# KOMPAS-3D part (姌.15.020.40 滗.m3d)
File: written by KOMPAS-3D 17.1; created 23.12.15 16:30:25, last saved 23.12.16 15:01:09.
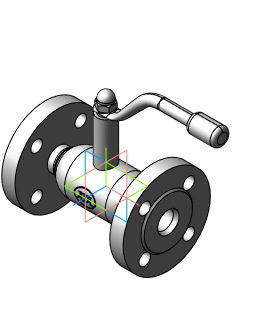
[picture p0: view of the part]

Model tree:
1. Операция без истории:3  (labels: Сталь 20  ГОСТ 1050-88)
